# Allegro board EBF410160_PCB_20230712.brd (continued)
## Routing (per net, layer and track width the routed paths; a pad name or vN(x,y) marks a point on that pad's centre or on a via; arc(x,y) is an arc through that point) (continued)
VCC_RTC: length 54.7
  TOP w0.254: v1(25.53,39.62) 27.56,39.62 28.13,39.05 J4.18
  TOP w0.381: R51.2 19.81,70.22 19.81,67.82 19.05,67.05 19.05,65.41 v1(18.28,64.64)
  ART03 w0.381: v1(18.28,64.64) 15.75,62.11 15.75,53.34 19.52,49.57 19.52,45.64 25.53,39.63 v1(25.53,39.62)
VCCA_1V8: length 87.9
  TOP w0.254: v1(26.42,23.11) 26.63,23.33 J4.12 ; v1(9.53,38.35) 8.89,38.99 8.89,45.85 6.73,48 R227.2
  ART03 w0.508: v1(26.42,23.11) 26.42,24.13 23.7,26.85 17.86,26.85 14.86,29.84 13.72,29.84 11.18,32.38 10.03,32.38 9.65,32.76 9.65,38.23 v1(9.53,38.35)
  ART03 w0.635: v1(54.86,16.13) 53.59,14.86 36.8,14.86 31.72,19.94 26.54,19.94 25.74,20.74 25.74,22.44 v1(26.42,23.11)
  BOTTOM w0.254: R34.1 52.07,23.63 52.07,21.72 52.32,21.46 54.36,21.46 54.86,20.95 v1(54.86,16.13)
  BOTTOM w0.381: v1(26.42,23.11) C50.1
VCCIO_ACODEC: length 126
  TOP w0.254: J4.21 29.13,21.87 v1(28.89,22.11) 28.88,22.11 28.63,21.86 J4.19
  TOP w0.381: v1(43.18,82.29) 43.18,76.2 45.59,73.79 45.59,70.86 45.09,70.37 C177.1 R214.1 C172.1 R212.1
  ART03 w0.635: v1(28.89,22.11) 28.19,22.81 28.19,26.92 27.14,27.98 18.12,27.98 14.73,31.37 13.84,31.37 12.45,32.76 12.45,38.23 9.78,40.89 9.78,47.49 6.1,51.17 6.1,66.8 7.24,67.94 7.24,70.1 7.87,70.74 11.18,70.74 21.37,80.94 34.71,80.94 36.07,82.29 v1(43.18,82.29)
VDD_3V3: length 128.4
  TOP w0.254: v1(127.82,45.03) 127.81,45.01 126.32,45.01 R165.1 R169.1 ; LED4.2 LED3.2 LED2.2 v1(129.02,14.72)
  TOP w0.381: v1(86.31,37.22) C107.1 R127.1 88.85,37.22 Q7.2 ; v1(17.28,64.64) 16.38,65.54 16.38,67.47 D9.2 ; v1(94.79,54.85) C88.1 93.14,54.85 L5.2
  TOP w0.508: v1(12.19,23.11) 11.53,23.77 11.53,26.52 v1(12.19,27.18) 13.84,28.83 v1(14.99,28.83)
  ART03 w0.508: v1(23.88,37.21) 25.02,36.07 v1(36.96,36.07) v1(40.39,36.07)
  POW04 w0.686: J34.1 100.73,10.65 ; J34.1 99.27,10.65 ; J34.1 100,9.93 ; 75.27,10.65 J32.1 ; J32.1 76.73,10.65 ; J32.1 76,9.93 ; 87.27,10.65 J33.1 ; J33.1 88.73,10.65 ; J33.1 88,9.93 ; 112,9.93 J35.1 ; J35.1 111.27,10.65 ; J35.1 112.73,10.65
  BOTTOM w0.254: C59.1 11.79,26.81 U10.5 ; C59.1 R42.1 ; C59.1 v1(12.19,27.18) ; R167.1 R163.1 v1(125.74,72.13) ; U13.16 25.28,38.22 24.88,38.62 C67.1 ; C73.1 50.05,38.62 50.3,38.36 U14.8 ; U9.5 11.79,22.74 C57.1 ; R155.1 50.17,65.9 50.67,65.4 52.71,65.4 53.21,65.9 R156.1 ; C57.1 v1(12.19,23.11) ; C57.1 R38.1
  BOTTOM w0.381: R47.2 121.71,12.69 120.78,11.76 v1(120.78,10.29) ; v1(36.96,36.07) 37.46,36.57 R52.1 R53.1 R55.1 R54.1 ; v1(66.93,65.91) 66.94,65.9 R158.1 ; C73.1 48.58,38.62 D23.2 ; v1(54.23,65.9) R156.1 ; v1(128.06,12.82) 127.93,12.69 R44.1 ; v1(74.55,66.16) 74.8,65.9 C92.1 76.07,65.91 76.45,66.29 77.25,66.29 L6.2
  BOTTOM w0.508: v1(14.99,28.83) 20.32,28.83 21.33,29.84 C6.1 ; v1(95.63,54.86) 95.62,54.85 v1(94.79,54.85) 93.98,54.05 93.98,51.56 86.31,43.9 v1(86.31,37.22) ; v1(23.88,37.21) C67.1 ; J35.1 110.38,10.65 109.77,11.26 C75.1
  vias: v1(22.86,37.21) v1(106.81,56.13)
VDD_5V: length 91.8
  TOP w0.508: v1(50.67,76.83) 52.07,75.44 52.07,68.96 51.44,68.32 51.44,64.13 ; 51.44,64.13 v1(51.42,64.13) ; 51.44,64.13 51.94,63.63 56.52,63.63 57.53,64.64 v1(66.42,64.64)
  ART03 w0.889: v1(16.26,64.64) 16.26,65.92 21.08,70.74 21.08,76.07 24.38,79.37 34.54,79.37 37.08,76.83 v1(50.67,76.83)
  BOTTOM w0.254: v1(51.42,64.13) 51.98,64.13 Q8.1
  BOTTOM w0.508: D32.2 v1(66.42,64.64) ; v1(16.26,64.64) 16.26,62.62 15.11,61.47 15.11,57.53 16.38,56.26 19.43,56.26 20.07,55.62 20.07,53.78
B_DM1: length 13.9
  TOP w0.158: J18.11 93.74,77.17 92.85,76.28 92.85,74.94 91.97,74.06 91.26,74.06 90.68,73.48 90.68,72.9 v1(90.93,72.64)
  BOTTOM w0.158: R129.1 89.23,69.03 89.23,69.46 89.6,69.83 89.77,69.83 arc(89.87,69.87) 89.91,69.97 arc(89.95,70.06) 90.04,70.1 90.4,70.1 arc(90.5,70.06) 90.54,69.97 arc(90.58,69.87) 90.67,69.83 91.1,69.83 91.37,70.1 91.37,70.55 U18.5 U18.6 91.35,71.41 91.35,72.48 91.18,72.64 v1(90.93,72.64)
B_DM2: length 14.4
  BOTTOM w0.158: R138.1 107.19,70.58 U20.4 U20.7 107.08,71.51 107.08,72.91 108.23,74.07 109.74,74.07 110.57,74.9 110.57,76.41 110.89,76.73 112.03,76.73 112.71,77.4 112.71,77.77 112.86,77.92 113.09,77.92 J20.8
B_DM3: length 10.6
  BOTTOM w0.158: J20.2 113.34,75.49 112.6,74.75 112.6,74.14 111.23,72.77 109.22,72.77 108.63,72.17 108.63,71.98 108.7,71.92 U20.10 U20.1 108.7,69.09 R131.1
B_DP1: length 13.9
  TOP w0.158: v1(90.17,72.64) 90.32,72.79 90.32,73.63 91.11,74.42 91.82,74.42 92.49,75.09 92.49,77.03 J18.12
  BOTTOM w0.158: R130.1 89.59,68.77 89.59,69.31 89.75,69.47 91.25,69.47 91.73,69.95 91.73,70.49 U18.4 U18.7 91.71,71.51 91.71,72.63 91.19,73.14 90.67,73.14 v1(90.17,72.64)
B_DP2: length 14.3
  BOTTOM w0.158: R139.1 106.17,69.34 106.7,69.86 U20.5 U20.6 106.7,71.64 106.72,71.66 106.72,73.06 108.08,74.43 109.59,74.43 110.21,75.05 110.21,76.56 110.74,77.09 111.88,77.09 112.34,77.55 112.34,77.8 J20.9
B_DP3: length 10.1
  BOTTOM w0.158: R132.1 108.33,68.7 108.33,70.1 108.2,70.24 U20.2 U20.9 108.2,71.92 108.27,71.98 108.27,72.32 109.07,73.13 111.08,73.13 112.24,74.29 112.24,74.9 J20.3
BD_CH3: length 4.5
  TOP w0.156: J6.20 v1(53.63,26.1)
  BOTTOM w0.254: v1(53.63,26.1) 53.59,26.07 C53.1 ; R35.1 C53.1 ; C53.1 R34.2
CAM0_NRST: length 105.9
  TOP w0.156: J7.35 57.63,62.84 57.91,63.12 69.98,63.12 70.23,62.86 v1(70.23,61.47)
  ART03 w0.142: v1(135,78.59) 135.68,77.91 135.68,66.21 132.72,63.24 128.65,63.24 127.08,61.68 125.55,61.68 125.13,62.1 112.39,62.1 112.01,62.48 101.09,62.48 98.55,59.94 85.6,59.94 84.12,58.46 77.39,58.46 76.07,57.15 72.14,57.15 70.23,59.05 v1(70.23,61.47)
  BOTTOM w0.156: J23.22 131.12,78.16 131.55,78.59 v1(135,78.59)
CAM0_PWDN: length 126.3
  TOP w0.156: v1(38.63,54.1) 37.63,55.1 J5.56
  ART03 w0.142: v1(133.35,57.4) 119,57.4 118.36,56.77 117.6,56.77 116.46,55.62 112.14,55.62 107.31,50.8 102.11,50.8 101.93,50.62 94.05,50.62 93.6,50.16 78.36,50.16 77.34,51.18 60.07,51.18 58.04,53.21 49.91,53.21 49.53,53.59 39.14,53.59 v1(38.63,54.1)
  BOTTOM w0.156: v1(133.35,57.4) 135.64,59.69 135.64,74.04 135.02,74.66 J23.15
CAM0_PWR_EN: length 78.7
  TOP w0.156: v1(81.53,39.88) 68.13,26.47 J6.78 ; v1(122.05,56.89) 122.05,56.39 121.28,55.62 v1(121.28,46.86)
  ART03 w0.142: v1(121.28,46.86) 120.78,46.35 118.24,46.35 117.73,45.85 116.2,45.85 114.14,43.78 114.14,42.45 113.8,42.12 112.31,42.12 110.45,40.26 81.92,40.26 v1(81.53,39.88)
  BOTTOM w0.156: v1(122.05,56.89) 121.54,57.4 R179.1
CAM1_NRST: length 78.6
  TOP w0.156: J7.41 59.13,59.59 v1(58.63,59.09)
  ART03 w0.142: v1(129.29,61.39) 127.96,60.07 105.66,60.07 102.74,57.15 90.96,57.15 90.16,56.34 85.68,56.34 84.69,55.35 67.84,55.35 65.53,57.66 64.26,57.66 63.37,58.55 59.18,58.55 v1(58.63,59.09)
  BOTTOM w0.156: J24.22 v1(129.29,61.39)
CAM1_PWDN: length 78.7
  TOP w0.156: v1(65.13,59.09) 64.63,59.59 J7.63
  ART03 w0.142: v1(131.95,60.32) 130.3,61.97 128.91,61.97 128.02,61.09 112.78,61.09 111.76,62.1 101.47,62.1 98.76,59.39 85.93,59.39 83.95,57.4 81.79,57.4 81.28,57.91 77.47,57.91 76.3,56.75 69.11,56.75 66.33,59.52 65.56,59.52 v1(65.13,59.09)
  BOTTOM w0.156: v1(131.95,60.32) 131.95,58.29 131.55,57.89 J24.15
CAM1_PWR_EN: length 116.5
  TOP w0.156: J5.12 26.63,55.21 v1(25.63,54.21)
  ART03 w0.142: v1(25.63,54.21) 25.63,47.01 26.8,45.85 50.67,45.85 55.76,40.76 69.85,40.76 70.36,41.27 92.58,41.27 93.22,41.91 v1(108.97,41.91)
  BOTTOM w0.156: R186.1 118.27,51.56 118.11,51.4 118.11,49.4 117.22,48.51 109.6,48.51 108.97,47.88 v1(108.97,41.91)
CC1: length 6.1
  TOP w0.156: v1(28.83,84.83) 28.58,84.58 J19.A5
  BOTTOM w0.156: v1(28.83,84.83) 28.83,82.68 29.62,81.89 D29.2
CC2: length 14.9
  TOP w0.156: J19.B5 v1(25.58,84.78)
  BOTTOM w0.156: v1(25.58,84.78) 25.58,86.03 25.91,86.36 28.96,86.36 29.34,85.98 29.34,82.93 30.54,81.72 30.54,79.98 D29.1
CSI_RX_D2N_S0: length 4.9
  BOTTOM w0.124: R178.2 126.28,76.15 126.8,76.15 127.38,75.57 129.51,75.57 129.6,75.66 J23.17
CSI_RX_D2N_S1: length 38.1
  TOP w0.124: v1(123.7,72.77) 123.7,73.05 122.64,74.1 122.64,74.11 122.23,74.52 122.23,75.8 122.54,76.11 122.88,76.11 v1(123.05,76.28)
  BOTTOM w0.124: R180.2 123.65,76.12 123.2,76.12 v1(123.05,76.28) ; v1(123.7,72.77) 123.7,73.03 123.38,73.34 123.21,73.34 121.98,72.12 arc(121.95,72.04) 121.98,71.97 arc(122.01,71.89) 121.98,71.82 121.78,71.62 arc(121.71,71.59) 121.63,71.62 arc(121.56,71.65) 121.48,71.62 121.28,71.42 arc(121.25,71.34) 121.28,71.27 arc(121.31,71.19) 121.28,71.12 121.08,70.91 arc(121.01,70.88) 120.93,70.91 arc(120.86,70.95) 120.78,70.91 120.27,70.4 120.27,69.79 120.39,69.67 121.73,69.67 122.05,69.35 122.05,68.83 121.73,68.52 120.39,68.52 120.14,68.27 120.14,57.53 121.37,56.3 129.51,56.3 129.6,56.39 J24.12
CSI_RX_D2P_S0: length 4.9
  BOTTOM w0.124: R176.2 126.36,75.82 126.66,75.82 127.24,75.24 129.51,75.24 129.6,75.16 J23.16
CSI_RX_D2P_S1: length 38.2
  TOP w0.124: v1(124.21,73.28) 123.93,73.28 122.97,74.24 122.97,74.24 122.56,74.66 122.56,75.66 122.68,75.78 122.88,75.78 v1(123.05,75.62)
  BOTTOM w0.124: R177.2 123.63,75.78 123.27,75.78 123.11,75.62 v1(123.05,75.62) ; v1(124.21,73.28) 123.91,73.28 123.52,73.67 123.07,73.67 119.94,70.54 119.94,69.66 120.26,69.34 121.6,69.34 121.72,69.22 121.72,68.97 121.6,68.85 120.26,68.85 119.81,68.4 119.81,57.39 121.23,55.98 129.51,55.98 129.6,55.89 J24.11
CSI_RX_D3N_S0: length 5.1
  BOTTOM w0.124: J23.20 129.6,77.16 129.51,77.07 128.42,77.07 127.34,78.14 126.32,78.14 R184.2
CSI_RX_D3N_S1: length 38.1
  TOP w0.124: v1(121.03,72.77) 121.03,73.79 121.28,74.04 121.28,77.29 122.14,78.14 122.88,78.14 v1(123.05,78.31)
  BOTTOM w0.124: R185.2 123.63,78.14 123.22,78.14 v1(123.05,78.31) ; v1(121.03,72.77) 121.03,72.95 121.02,72.95 120.9,73.08 120.45,73.08 119.25,71.88 119.25,71.63 arc(119.31,71.5) 119.44,71.44 arc(119.53,71.4) 119.57,71.32 119.57,71.07 arc(119.53,70.98) 119.44,70.94 arc(119.31,70.89) 119.25,70.75 119.25,56.89 121.84,54.3 129.51,54.3 129.6,54.39 J24.8
CSI_RX_D3P_S0: length 5.1
  BOTTOM w0.124: R182.2 126.32,77.81 127.21,77.81 128.28,76.74 129.51,76.74 129.6,76.66 J23.19
CSI_RX_D3P_S1: length 38
  TOP w0.124: v1(121.54,73.28) 121.61,73.35 121.61,77.15 122.28,77.82 122.88,77.82 v1(123.05,77.65)
  BOTTOM w0.124: J24.7 129.6,53.89 129.51,53.98 121.71,53.98 118.93,56.76 118.93,72.02 120.31,73.4 121.03,73.4 121.16,73.28 v1(121.54,73.28) ; R183.2 123.63,77.81 123.28,77.81 123.11,77.65 v1(123.05,77.65)
CTP0_INT: length 134.9
  TOP w0.156: J21.11 128.81,69.12 v1(128.02,68.32) 122.43,68.32 118.75,64.64 118.75,52.2 119.25,51.69 119.25,49.4 118.24,48.39 v1(118.24,44.83) ; J6.65 v1(65.13,19.18)
  ART03 w0.142: v1(118.24,44.83) 118.36,44.7 118.36,43.05 123.7,37.72 127,37.72 129.03,35.68 129.03,19.94 126.11,17.02 121.54,17.02 119.89,15.37 78.49,15.37 77.98,15.87 74.3,15.87 70.99,19.18 v1(65.13,19.18)
  BOTTOM w0.156: v1(128.02,68.32) R162.2
CTP0_RST: length 139.9
  TOP w0.156: J21.12 v1(128.07,69.62) 128.07,69.62 127.28,68.83 122.3,68.83 118.21,64.74 118.21,49.17 117.73,48.69 117.73,45.34 v1(117.22,44.83) ; J6.61 v1(64.13,19.18)
  ART03 w0.142: v1(117.22,44.83) 117.73,45.34 118.49,45.34 118.75,45.08 118.75,43.31 122.94,39.11 126.36,39.11 129.54,35.94 129.54,19.81 126.24,16.51 121.67,16.51 120.02,14.86 78.11,14.86 77.69,15.28 74.13,15.28 70.74,18.67 64.64,18.67 v1(64.13,19.18)
  BOTTOM w0.156: v1(128.07,69.62) 127.79,69.34 R166.2
CTP1_INT: length 111.7
  TOP w0.156: J7.55 v1(62.63,60.11) ; R164.2 127.31,47.62 v1(127.91,47.03) J22.11
  BOTTOM w0.156: v1(127.91,47.03) 128.37,47.49 128.37,48.23 128.09,48.51 118.49,48.51 117.86,47.88 112.39,47.88 109.86,45.34 109.86,34.59 109.43,34.16 94.92,34.16 93.4,32.64 77.85,32.64 64.66,45.83 61.61,45.83 57.66,49.78 57.66,55.82 58.43,56.6 61.42,56.6 63.11,58.29 63.11,59.63 v1(62.63,60.11)
CTP1_RST: length 110.9
  TOP w0.156: J7.57 63.13,59.59 v1(62.63,59.09) ; J22.12 128.39,47.53 v1(127.89,48.02) 127.27,48.64 R168.2
  BOTTOM w0.156: v1(62.63,59.09) 62.63,58.44 61.21,57.02 58.04,57.02 57.15,56.13 57.15,49.53 61.3,45.38 64.35,45.38 77.6,32.13 93.65,32.13 95.17,33.65 109.64,33.65 110.36,34.38 110.36,45.08 112.65,47.37 118.11,47.37 118.77,48.02 v1(127.89,48.02)
DBG_RX: length 2.8
  BOTTOM w0.156: R40.2 8.88,25.91 9.86,25.91 10.29,25.48 U10.2
DBG_RXD: length 5.5
  BOTTOM w0.156: J9.3 3.52,25.41 D6.2 R40.1
DBG_TX: length 1.4
  BOTTOM w0.156: R39.2 8.78,22.74 U9.4
DBG_TXD: length 5.8
  BOTTOM w0.156: R39.1 D5.2 6.32,22.39 J9.2
DM4: length 9.5
  TOP w0.158: J27.36 98.8,61.91 98.58,61.69 98.58,59.59 98.74,59.43 99.06,59.43 99.31,59.18 D38.2 98.84,58.66 98.68,58.51 98.68,57.15 98.15,56.62 98.15,55.76 98.28,55.63 98.57,55.63 R210.1
DP4: length 10.4
  TOP w0.158: R211.1 98.43,55.24 98.16,55.24 97.79,55.61 97.79,56.77 98.32,57.3 98.32,58.51 98.16,58.66 D39.2 97.66,59.28 97.82,59.43 98.04,59.43 98.22,59.61 98.22,60.32 arc(98.18,60.42) 98.07,60.47 arc(97.96,60.51) 97.92,60.62 97.92,60.95 arc(97.96,61.06) 98.07,61.1 arc(98.18,61.15) 98.22,61.25 98.22,61.69 98,61.91 J27.38
DSI0_RST: length 107.5
  TOP w0.156: J5.60 v1(38.63,56.13) ; J21.15 122.43,71.12 116.71,65.4 116.71,61.72 115.82,60.83 115.82,57.02 v1(115.44,56.64)
  ART03 w0.142: v1(115.44,56.64) 111.51,56.64 107.03,52.16 93.51,52.16 92.61,51.26 78.53,51.26 77.77,52.02 63.29,52.02 61.72,53.59 59.18,53.59 58.12,54.65 40.11,54.65 v1(38.63,56.13)
DSI0_TE: length 102
  TOP w0.156: J5.58 38.13,55.62 v1(38.63,55.12) ; R160.1 122.3,70.23 117.22,65.15 117.22,61.21 116.59,60.58 v1(116.59,56.64)
  ART03 w0.142: v1(116.59,56.64) 116.08,56.13 111.89,56.13 107.5,51.75 102.17,51.75 101.6,51.18 97.92,51.18 97.62,51.48 93.77,51.48 93.11,50.82 78.34,50.82 77.58,51.58 62.85,51.58 61.34,53.08 58.93,53.08 58.29,53.72 50.16,53.72 49.78,54.1 39.65,54.1 v1(38.63,55.12)
DSI1_RST: length 115.4
  TOP w0.156: J22.15 128.47,49.02 127.2,50.29 122.43,50.29 121.77,49.63 121.77,46.33 v1(121.28,45.85) ; v1(61.63,59.09) 62.13,59.59 J7.53
  BOTTOM w0.156: v1(61.63,59.09) 61.63,58.71 60.71,57.78 57.28,57.78 56.13,56.64 56.13,49.1 60.91,44.32 63.5,44.32 76.71,31.11 94.28,31.11 95.68,32.51 110.11,32.51 111.38,33.78 111.38,44.58 112.65,45.85 118.11,45.85 118.59,46.33 120.8,46.33 v1(121.28,45.85)
DSI1_TE: length 108.6
  TOP w0.156: R161.1 122.81,49.66 122.3,49.15 v1(122.3,46.86) ; J7.51 v1(61.63,60.11)
  BOTTOM w0.156: v1(122.3,46.86) 121.82,47.35 118.85,47.35 117.86,46.35 112.39,46.35 110.87,44.83 110.87,34.17 109.85,33.15 95.55,33.15 94.03,31.62 77.22,31.62 64.01,44.83 61.09,44.83 56.64,49.27 56.64,56.39 57.66,57.4 60.96,57.4 62.11,58.56 62.11,59.63 v1(61.63,60.11)
EDP_AUXN: length 7.6
  TOP w0.124: C146.2 123.69,24.42 123.81,24.29 126.74,24.29 126.86,24.42 R191.2 127.25,24.89 127.8,24.34 129.06,24.34 129.14,24.43 J25.10
EDP_AUXP: length 7.6
  TOP w0.124: C147.2 123.69,23.84 123.81,23.97 126.74,23.97 126.86,23.84 R188.2 127.25,23.37 127.9,24.01 129.06,24.01 129.14,23.93 J25.9
EDP_BL_EN: length 118.3
  TOP w0.156: J25.22 130.89,30.43 v1(131.06,30.61) ; v1(33.63,19.05) J4.39
  ART03 w0.142: v1(33.63,19.05) 34.65,18.03 50.29,18.03 51.18,17.14 68.45,17.14 72.77,12.83 120.65,12.83 122.43,14.6 127.38,14.6 132.21,19.43 132.21,28.7 131.7,29.21 131.7,29.97 v1(131.06,30.61)
EDP_BL_PWM: length 134.9
  TOP w0.156: J5.5 25.13,63.26 v1(26.13,64.26) ; v1(127.89,31.24) 128.2,30.93 J25.23
  ART03 w0.142: v1(26.13,64.26) 25.65,63.78 25.65,55.12 25.15,54.61 25.15,46.74 27.3,44.58 51.18,44.58 56.39,39.37 110.87,39.37 111.25,39.75 112.52,39.75 114.35,37.92 120.83,37.92 122.94,35.81 127.13,35.81 127.89,35.05 v1(127.89,31.24)
EDP_HPDIN_M0: length 99.2
  TOP w0.156: v1(68.45,31.49) 65.13,28.17 J6.66 ; J25.17 v1(131.7,27.93)
  ART03 w0.142: v1(73.41,13.69) 73.76,13.33 120.52,13.33 122.3,15.11 127.13,15.11
  ART03 w0.156: 127.13,15.11 131.7,19.68 v1(131.7,27.93)
  BOTTOM w0.156: v1(68.45,31.49) 71.12,28.83 71.12,28.45 71.2,28.37 71.2,27.97 71.12,27.89 71.12,20.45 73.41,18.16 v1(73.41,13.69)
EDP_PWR_EN: length 69.4
  TOP w0.156: R196.1 118.57,27.68 118.31,27.93 118.31,36.57 117.68,37.21 112.52,37.21 v1(112.01,37.72) ; v1(78.36,37.72) 67.63,26.99 J6.76
  ART03 w0.142: v1(78.36,37.72) v1(112.01,37.72)
  BOTTOM w0.156: v1(112.01,37.72) R192.1
EDP_TP_INT: length 114
  TOP w0.156: J7.65 v1(65.13,60.11) ; v1(88.9,33.27) 88.9,12.95 88.39,12.44 69.85,12.44 68.96,11.56 68.96,10.2 68.41,9.65 63,9.65 J26.2
  BOTTOM w0.156: v1(88.9,33.27) 77.98,33.27 65.02,46.23 61.98,46.23 58.29,49.91 58.29,54.95 59.48,56.13 61.47,56.13 61.97,56.64 62.23,56.64 64.26,58.67 64.26,59.24 v1(65.13,60.11) ; J26.2 63.37,12.03 63.37,18.03 61.84,19.57 R189.2
EDP_TP_RESET: length 15.2
  TOP w0.156: J6.57 v1(63.13,22.1)
  BOTTOM w0.156: R190.2 62.37,21.33 v1(63.13,22.1) 63.63,21.6 63.63,18.67 64.39,17.91 64.39,11.04 J26.3
EDP_TX_AUXN: length 81.1
  TOP w0.124: J6.62 64.13,25.81 64.06,25.88 64.06,29.26 64.91,30.11 64.91,31.18 v1(65.1,31.37) ; v1(120,22.2) 120.14,22.34 120.14,23.75 120.69,24.29 122.57,24.29 122.69,24.42 C146.1
  ART03 w0.113: v1(65.1,31.37) 64.77,31.7 64.77,32.06 65.15,32.45 65.61,32.45 arc(65.68,32.42) 65.71,32.35 arc(65.74,32.29) 65.8,32.26 66.06,32.26 arc(66.13,32.29) 66.16,32.35 arc(66.19,32.42) 66.25,32.45 66.51,32.45 arc(66.58,32.42) 66.61,32.35 arc(66.64,32.29) 66.71,32.26 66.96,32.26 arc(67.03,32.29) 67.06,32.35 arc(67.09,32.42) 67.16,32.45 96.14,32.45 97.92,34.23 116.2,34.23 117.72,32.71 117.72,27.51 118.78,26.44 118.78,26.29 118.34,25.85 118.34,25.43 118.68,25.08 119.1,25.08 119.54,25.52 119.7,25.52 120.21,25.01 120.21,22.4 120.01,22.2 v1(120,22.2)
EDP_TX_AUXP: length 81
  TOP w0.124: J6.60 63.63,25.78 63.73,25.88 63.73,29.4 64.58,30.24 64.58,31.23 v1(64.44,31.37) ; v1(120.66,22.2) 120.47,22.4 120.47,23.61 120.82,23.97 122.57,23.97 122.69,23.84 C147.1
  ART03 w0.113: v1(64.44,31.37) 64.45,31.38 64.45,32.2 65.02,32.76 96.01,32.76 97.79,34.54 116.33,34.54 118.03,32.84 118.03,27.64 119.09,26.58 119.09,26.15 118.65,25.72 118.65,25.56 118.81,25.4 118.97,25.4 119.41,25.84 119.83,25.84 120.52,25.14 120.52,22.34 v1(120.66,22.2)
EDP_TX_D0N: length 88.8
  TOP w0.124: v1(128.51,22.35) 128.69,22.53 129.88,22.53 J25.6 ; J6.44 59.63,25.81 59.54,25.9 59.54,31.2 v1(59.71,31.37)
  ART03 w0.113: v1(128.51,22.35) 128.21,22.65 127.4,22.65 126.08,23.97 124.04,23.97 119.45,28.57 119.45,33.46 116.33,36.57 97.35,36.57 95.89,35.12 62.55,35.12 59.54,32.1 59.54,31.54 v1(59.71,31.37)
EDP_TX_D0P: length 89.2
  TOP w0.124: v1(128.51,23.01) 128.66,22.86 129.92,22.86 J25.7 ; v1(59.05,31.37) 59.22,31.2 59.22,25.9 59.13,25.81 J6.42
  ART03 w0.113: v1(59.05,31.37) 59.22,31.54 59.22,32.24 62.42,35.43 95.76,35.43 97.22,36.89 116.46,36.89 119.76,33.59 119.76,28.7 124.18,24.29 126.21,24.29 127.53,22.96 128.46,22.96 v1(128.51,23.01)
EDP_TX_D1N: length 90.1
  TOP w0.124: v1(62.36,31.37) 62.17,31.18 62.17,29.91 60.54,28.28 60.54,25.9 60.63,25.81 J6.48 ; J25.3 129.88,21.03 126.79,21.03 v1(126.6,20.85)
  ART03 w0.113: v1(126.6,20.85) 126.36,21.1 125.52,21.1 124.21,22.4 124.05,22.4 123.57,21.92 123.15,21.92 122.8,22.26 122.8,22.68 123.29,23.17 123.29,23.33 123.13,23.49 122.97,23.49 122.55,23.07 122.13,23.07 121.78,23.41 121.78,23.83 122.2,24.26 122.2,24.41 118.54,28.08 118.54,33.1 116.52,35.12 97.41,35.12 96.27,33.97 63.31,33.97 62.1,32.76 62.1,31.63 v1(62.36,31.37)
EDP_TX_D1P: length 90.5
  TOP w0.124: J25.4 129.92,21.36 126.75,21.36 v1(126.6,21.51) ; v1(61.7,31.37) 61.84,31.23 61.84,30.05 60.22,28.42 60.22,25.9 60.13,25.81 J6.46
  ART03 w0.113: v1(61.7,31.37) 61.79,31.45 61.79,32.9 63.18,34.29 96.14,34.29 97.28,35.43 116.65,35.43 118.86,33.23 118.86,28.21 122.52,24.55 122.52,24.12 122.1,23.7 122.1,23.54 122.26,23.38 122.42,23.38 122.84,23.81 123.26,23.81 123.6,23.46 123.6,23.04 123.12,22.55 123.12,22.39 123.28,22.23 123.44,22.23 123.92,22.72 124.34,22.72 125.65,21.41 126.51,21.41 v1(126.6,21.51)
EXT_PWR_EN: length 81.8
  TOP w0.156: J4.27 v1(30.63,22.1) ; v1(14.48,37.84) 13.72,38.61 R19.1
  ART03 w0.142: v1(30.63,22.1) 30.63,27.51 28.02,30.12 20.09,30.12 15.72,34.49 14.53,34.49 13.97,35.05 13.97,37.34 v1(14.48,37.84) 14.99,38.35 14.99,42.92 15.62,43.56 v1(15.62,45.72) 15.62,48.39 10.03,53.97 10.03,67.05 v1(9.4,67.69)
  BOTTOM w0.156: R3.1 15.75,48.51 15.62,48.39 v1(15.62,45.72) 20.95,45.72 21.33,45.35 R1.1 ; R24.1 5.2,67.45 9.16,67.45 v1(9.4,67.69)
FSPI_CLK: length 36
  TOP w0.156: U8.6 82.42,25.4 v1(80.14,27.68) ; v1(56.63,23.12) 56.13,22.62 J6.29
  ART03 w0.142: v1(56.63,23.12) 56.63,24.24 57.91,25.53 59.48,25.53 59.62,25.67 59.62,26.02 59.77,26.16 60.05,26.16 60.19,26.02 60.19,25.67 60.34,25.53 60.62,25.53 60.76,25.67 60.76,26.02 60.91,26.16 61.19,26.16 61.33,26.02 61.33,25.67 61.48,25.53 68.65,25.53 70.81,27.68 v1(80.14,27.68)
FSPI_CS0N: length 36.2
  TOP w0.156: J6.31 v1(56.63,22.1) ; v1(83.69,27.68) 84.96,28.95 U8.1
  ART03 w0.142: v1(56.63,22.1) 57.13,22.6 57.13,23.85 58.29,25.02 68.96,25.02 71.12,27.18 81.03,27.18 82.04,28.19 83.19,28.19 v1(83.69,27.68)
FSPI_D0: length 45.1
  TOP w0.156: J6.33 57.13,22.62 v1(57.63,23.12) ; v1(80.14,26.67) 81.15,25.65 U8.5
  ART03 w0.142: v1(80.14,26.67) 80.14,25.91 80.01,25.78 79.63,25.78 79.5,25.91 79.5,26.54 79.38,26.67 79.03,26.67 78.89,26.53 78.89,25.92 78.74,25.78 78.46,25.78 78.32,25.92 78.32,26.53 78.17,26.67 77.89,26.67 77.75,26.53 77.75,25.92 77.6,25.78 77.32,25.78 77.18,25.92 77.18,26.53 77.03,26.67 71.44,26.67 69.16,24.38 58.29,24.38 57.63,23.72 v1(57.63,23.12)
  BOTTOM w0.156: J8.2 81.79,25.02 v1(80.14,26.67)
FSPI_D1: length 36.1
  TOP w0.156: J6.35 v1(57.63,22.1) ; 83.69,31.3 83.69,28.95 v1(82.42,27.68)
  ART03 w0.142: v1(82.42,27.68) 81.41,26.67 80.91,26.67 80.77,26.53 80.77,26.16 80.9,26.03 81.41,26.03 81.53,25.91 81.53,25.41 81.39,25.27 77.09,25.27 76.2,26.16 71.64,26.16 69.36,23.87 58.42,23.87 58.15,23.61 58.15,22.63 v1(57.63,22.1)
FSPI_D2: length 46.2
  TOP w0.156: v1(58.63,23.12) 58.13,22.62 J6.37 ; R36.2 87.5,32.38 87,32.89 82.8,32.89 82.42,32.51 U8.3 82.42,29.59 81.79,28.95 81.79,27.3 v1(82.42,26.67)
  ART03 w0.142: v1(82.42,26.67) 83.04,26.67 83.19,26.53 83.19,26.16 83.06,26.03 82.18,26.03 82.04,25.89 82.04,25.02 81.79,24.76 76.83,24.76 75.95,25.65 71.84,25.65 69.56,23.37 58.88,23.37 v1(58.63,23.12)
FSPI_D3: length 39.6
  TOP w0.156: J6.39 v1(58.63,22.1) ; R37.2 85.97,28.95 v1(83.69,26.67) 83.69,23.3
  ART03 w0.142: v1(58.63,22.1) 59.38,22.86 69.72,22.86 72.01,25.14 75.69,25.14 76.58,24.26 83.55,24.26 83.69,24.4 83.69,24.76 83.57,24.89 82.68,24.89 82.55,25.02 82.55,25.38 82.69,25.53 83.57,25.53 83.69,25.65 v1(83.69,26.67)
GMAC1_INT: length 106.7
  TOP w0.156: v1(24.13,54.21) 24.74,54.21 26.13,55.59 J5.10 ; R111.1 90.55,55.88 90.81,55.62 91.95,55.62 92.33,56.01 93.6,56.01 93.98,55.62 96.01,55.62 96.27,55.37 96.27,53.47 v1(95.63,52.83)
  ART03 w0.142: v1(95.63,52.83) 91.82,52.83 91.44,52.45 64.64,52.45 63.58,53.51 62.95,53.51 60.82,55.64 40.88,55.64 40.64,55.88 40.64,56.26 40.26,56.64 39.75,56.64 34.16,62.23 34.16,66.29 33.15,67.31 26.67,67.31 25.15,65.78 25.15,55.22 v1(24.13,54.21)
GMAC1_MCLKINOUT_M1: length 48.6
  TOP w0.156: R112.1 R113.1 v1(95.12,56.13) ; J7.56 62.63,55.35 63.37,54.61 64.11,54.61 64.39,54.33 v1(64.39,48.41)
  BOTTOM w0.156: v1(95.12,56.13) 94.64,55.65 93.8,55.65 92.08,53.92 92.08,51.56 87.5,46.99 79.88,46.99 78.46,48.41 v1(64.39,48.41)
GMAC1_MDC_M1: length 24
  TOP w0.156: v1(64.63,55.09) 64.13,55.59 J7.62 ; U16.13 79.87,58.16 79.12,58.16 77.98,57.02 v1(77.98,56.95) 77.85,56.82 77.85,54.73 R108.2
  BOTTOM w0.156: v1(77.98,56.95) 76.66,55.62 66.06,55.62 65.53,55.09 v1(64.63,55.09)
GMAC1_MDIO_M1: length 25
  TOP w0.156: U16.14 79.21,56.95 v1(78.99,56.95) 78.36,56.31 78.36,54.86 78.87,54.35 79.24,54.35 R109.2 ; J7.60 v1(63.63,56.11)
  BOTTOM w0.156: v1(78.99,56.95) 78.41,57.53 77.72,57.53 76.33,56.13 65.79,56.13 65.28,55.62 64.12,55.62 v1(63.63,56.11)
GMAC1_RSTN: length 67.6
  TOP w0.156: J5.4 24.63,58.28 24.64,58.29 v1(24.64,59.18)
  BOTTOM w0.156: v1(24.64,59.18) 24.64,47.62 25.91,46.35 47.5,46.35 48.64,47.5 48.64,58.8 51.68,61.84 C84.1 65.21,61.84 D28.1
GMAC1_RXCLK_M1: length 37.4
  TOP w0.156: R101.1 v1(86.11,51.81) R95.2 ; J7.36 57.63,54.51 59.18,52.96 60.96,52.96 61.98,51.94 v1(61.98,49.91)
  BOTTOM w0.156: v1(61.98,49.91) 62.46,49.43 76.35,49.43 76.71,49.78 84.07,49.78 v1(86.11,51.81)
GMAC1_RXD0_M1: length 38.8
  TOP w0.156: v1(59.56,52.45) 58.8,52.45 57.13,54.12 J7.34 ; R93.2 v1(84.07,51.81) R96.1
  BOTTOM w0.156: v1(59.56,52.45) 59,51.89 59,51.67 59.21,51.46 59.43,51.46 59.92,51.94 67.51,51.94 67.67,52.1 67.67,52.34 67.82,52.5 68.14,52.5 68.29,52.34 68.29,52.1 68.45,51.94 68.76,51.94 68.92,52.1 68.92,52.34 69.08,52.5 69.39,52.5 69.55,52.34 69.55,52.1 69.7,51.94 70.01,51.94 70.17,52.1 70.17,52.34 70.33,52.5 70.64,52.5 70.8,52.34 70.8,52.1 70.95,51.94 73.41,51.94 74.04,52.58 80.55,52.58 80.7,52.73 80.7,53.31 80.86,53.47 81.17,53.47 81.33,53.31 81.33,52.61 81.49,52.45 83.44,52.45 v1(84.07,51.81)
GMAC1_RXD1_M1: length 36.3
  TOP w0.156: R94.2 v1(83.06,51.81) R97.1 ; J7.32 56.63,53.86 58.55,51.94 61.09,51.94 61.34,51.69 61.34,50.67 v1(60.58,49.91)
  BOTTOM w0.156: v1(60.58,49.91) 61.16,50.5 76.09,50.5 76.32,50.72 81.96,50.72 v1(83.06,51.81)
GMAC1_RXD2_M1: length 37.2
  TOP w0.156: v1(59.56,49.91) 59.56,50.24 59.99,50.67 60.68,50.67 60.83,50.83 60.83,51.28 60.68,51.43 58.29,51.43 57.95,51.78 57.57,51.78 57.32,52.03 57.32,52.41 57.07,52.66 56.68,52.66 56.43,52.91 56.43,53.29 56.13,53.6 J7.30 ; R103.1 v1(82.04,51.81) R99.1
  BOTTOM w0.156: v1(59.56,49.91) 60.62,50.96 75.9,50.96 76.12,51.19 81.42,51.19 v1(82.04,51.81)
GMAC1_RXD3_M1: length 36.4
  TOP w0.156: v1(59.56,50.93) 57.66,50.93 57.29,51.3 57.03,51.3 56.72,51.61 56.72,51.87 56.4,52.18 56.15,52.18 55.83,52.5 55.83,52.75 55.63,52.95 J7.28 ; R100.1 v1(81.03,51.81) R104.1
  BOTTOM w0.156: v1(81.03,51.81) 80.73,52.11 80.44,52.11 80.28,51.95 80.28,51.82 80.12,51.66 79.81,51.66 79.65,51.82 79.65,51.95 79.5,52.11 79.18,52.11 79.03,51.95 79.03,51.82 78.87,51.66 78.56,51.66 78.4,51.82 78.4,51.95 78.24,52.11 77.93,52.11 77.78,51.95 77.78,51.82 77.62,51.66 77.31,51.66 77.15,51.82 77.15,51.95 76.99,52.11 76.68,52.11 76.52,51.95 76.52,51.82 76.37,51.66 76.05,51.66 75.9,51.82 75.9,51.95 75.74,52.11 75.46,52.11 75.3,51.95 75.3,51.59 75.14,51.43 74.83,51.43 74.68,51.59 74.68,51.95 74.52,52.11 74.24,52.11 73.6,51.47 60.11,51.47 v1(59.56,50.93)
GMAC1_RXDV_CRS_M1: length 38.9
  TOP w0.156: v1(63.12,49.91) 62.61,50.42 62.61,50.85 62.77,51 63.6,51 63.75,51.16 63.75,51.47 63.6,51.63 62.77,51.63 62.61,51.79 62.61,52.32 61.47,53.47 59.44,53.47 58.13,54.77 J7.38 ; R105.1 v1(85.09,51.81) R102.1
  BOTTOM w0.156: v1(63.12,49.91) 76.17,49.91 76.51,50.25 83.47,50.25 83.63,50.41 83.63,50.61 83.25,50.99 83.25,51.21 83.47,51.43 83.69,51.43 84.27,50.86 84.49,50.86 85.09,51.46 v1(85.09,51.81)
GMAC1_TXCLK_M1: length 29.5
  TOP w0.156: J7.44 v1(59.63,54.1) ; U16.20 81.92,56.25 81.92,55.8 v1(81.03,54.92)
  BOTTOM w0.156: v1(81.03,54.92) 81.03,54.48 79.61,53.06 67.41,53.06 66.93,52.58 61.21,52.58 60.83,52.96 60.2,52.96 59.63,53.53 v1(59.63,54.1)
GMAC1_TXD0_M1: length 25.5
  TOP w0.156: U16.18 80.94,56.42 80.79,56.42 80.52,56.15 80.52,55.42 v1(80.01,54.92) ; J7.52 61.63,55.24 61.88,54.99 62.23,54.99 62.48,54.74 62.48,54.38 62.79,54.08 v1(63.12,54.08)
  BOTTOM w0.156: v1(80.01,54.92) 79.53,55.4 78.77,55.4 77.98,54.61 66.55,54.61 66.02,54.08 v1(63.12,54.08)
GMAC1_TXD1_M1: length 27.3
  TOP w0.156: U16.17 80.73,56.77 80.52,56.77 80.01,56.26 v1(80.01,55.93) ; J7.50 61.13,55.07 v1(63.12,53.08)
  BOTTOM w0.156: v1(80.01,55.93) 80.52,55.42 80.52,54.74 79.36,53.58 67.04,53.58 66.55,53.08 v1(63.12,53.08)
GMAC1_TXD2_M1: length 28.2
  TOP w0.156: U16.16 80.55,57.15 80.39,57.15 79.5,56.26 79.5,55.42 v1(78.99,54.92) ; J7.48 v1(60.63,55.09)
  BOTTOM w0.156: v1(78.99,54.92) 78.18,54.1 66.8,54.1 66.29,53.59 62.13,53.59 61.98,53.44 61.98,53.24 61.82,53.08 61.51,53.08 61.35,53.24 61.35,53.44 61.19,53.59 60.33,53.59 60.15,53.77 60.15,54.61 v1(60.63,55.09)
GMAC1_TXD3_M1: length 28.6
  TOP w0.156: U16.15 80.36,57.53 80.26,57.53 78.99,56.26 v1(78.99,55.93) ; v1(60.63,54.08) 60.13,54.58 J7.46
  BOTTOM w0.156: v1(60.63,54.08) 61.09,54.08 61.21,54.21 61.21,54.83 61.37,54.99 61.69,54.99 61.85,54.83 61.85,54.26 62.01,54.1 62.36,54.1 62.82,54.56 65.74,54.56 66.29,55.12 77.72,55.12 78.18,55.58 78.18,55.8 77.97,56.01 77.97,56.23 78.22,56.48 78.45,56.48 v1(78.99,55.93)
GMAC1_TXEN_M1: length 29.3
  TOP w0.156: U16.19 v1(81.03,55.93) ; v1(59.15,55.12) 59.13,55.13 J7.42
  BOTTOM w0.156: v1(81.03,55.93) 78.79,58.16 77.6,58.16 76.07,56.64 65.05,56.64 64.89,56.8 64.89,57.25 64.74,57.4 64.42,57.4 64.27,57.25 64.27,56.8 64.11,56.64 63.35,56.64 62.28,55.58 60.28,55.58 59.82,55.12 v1(59.15,55.12)
GPIO2_B7: length 114.2
  TOP w0.156: R48.2 124.84,19.56 124.46,19.94 120.27,19.94 119.63,19.3 119.63,16.89 118.62,15.87 114.17,15.87 113.16,16.89 113.16,23.24 v1(112.39,24) ; J7.47 v1(60.63,60.11)
  BOTTOM w0.156: v1(60.63,60.11) 61.11,59.63 61.11,58.89 60.39,58.16 57.02,58.16 55.63,56.77 55.63,48.89 60.71,43.81 63.12,43.81 76.33,30.61 94.54,30.61 95.94,32 112.27,32 113.41,30.86 113.41,27.81 112.39,26.8 v1(112.39,24)
GPIO2_C0: length 111.5
  TOP w0.156: R49.2 120.64,19.04 120.27,18.67 120.27,16.64 118.87,15.24 113.92,15.24 112.52,16.64 112.52,22.86 v1(111.38,24) ; J7.49 61.13,59.59 v1(60.63,59.09)
  BOTTOM w0.156: v1(111.38,24) 111.38,26.54 112.9,28.07 112.9,30.35 111.89,31.37 96.19,31.37 94.92,30.1 76.12,30.1 62.91,43.31 60.58,43.31 54.65,49.24 54.65,56.55 56.64,58.55 60.08,58.55 v1(60.63,59.09)
HDMI_5V: length 34.1
  TOP w0.381: v1(59.44,68.96) 60.07,68.32 v1(64.64,68.32) 68.77,68.32 v1(71.18,65.91)
  BOTTOM w0.254: R159.1 71.9,64.41 Q10.1 v1(71.18,65.91) ; Q9.1 56.58,65.34 57.14,65.9 R157.1 57.78,67.31 v1(59.44,68.96)
  BOTTOM w0.508: U25.18 61.84,68.34 63.88,66.29 D37.2 C129.1 ; C129.1 65.35,65.9 D32.1 ; C129.1 64.9,68.07 v1(64.64,68.32)
HDMI_TX0N_PORT: length 46.4
  TOP w0.124: J5.48 35.63,56.46 35.55,56.39 35.55,54.23 v1(35.69,54.1)
  BOTTOM w0.124: U25.9 60.42,77.25 59.8,77.25 56.42,73.86 55.82,73.86 55.73,73.78 U27.7 U27.4 53.98,73.78 53.9,73.86 53.63,73.86 51.44,71.67 51.44,69.47 50.98,69.01 48.58,69.01 arc(48.52,68.99) 48.49,68.92 arc(48.46,68.86) 48.4,68.83 48.09,68.83 arc(48.02,68.86) 48,68.92 arc(47.97,68.99) 47.9,69.01 45.77,69.01 arc(45.73,69.01) 45.7,68.98 45.09,68.37 45.09,67.97 arc(45.12,67.88) 45.21,67.84 arc(45.3,67.81) 45.34,67.72 45.34,67.47 arc(45.3,67.39) 45.21,67.35 arc(45.12,67.31) 45.09,67.22 45.09,66.98 arc(45.12,66.89) 45.21,66.85 arc(45.3,66.81) 45.34,66.73 45.34,66.48 arc(45.3,66.39) 45.21,66.36 arc(45.12,66.32) 45.09,66.23 45.09,65.99 arc(45.12,65.9) 45.21,65.86 arc(45.3,65.82) 45.34,65.73 45.34,65.49 arc(45.3,65.4) 45.21,65.36 arc(45.12,65.33) 45.09,65.24 45.09,65 arc(45.12,64.91) 45.21,64.87 arc(45.3,64.83) 45.34,64.74 45.34,64.5 arc(45.3,64.41) 45.21,64.37 arc(45.12,64.34) 45.09,64.25 45.09,63.8 42.3,61.01 41.69,61.01 39.66,58.98 37.73,58.98 37.34,58.6 arc(37.3,58.49) 37.34,58.38 arc(37.39,58.28) 37.34,58.17 37.21,58.03 arc(37.1,57.99) 36.99,58.03 arc(36.89,58.08) 36.78,58.03 36.64,57.9 arc(36.6,57.79) 36.64,57.68 arc(36.69,57.58) 36.64,57.47 36.51,57.33 arc(36.4,57.29) 36.29,57.33 arc(36.19,57.38) 36.08,57.33 35.54,56.8 35.54,54.24 v1(35.69,54.1)
HDMI_TX0P_PORT: length 44.9
  TOP w0.124: v1(35.03,54.1) 35.23,54.3 35.23,56.33 35.13,56.43 J5.46
  BOTTOM w0.124: v1(35.03,54.1) 35.22,54.29 35.22,56.93 37.59,59.31 39.52,59.31 41.56,61.34 42.16,61.34 44.76,63.93 44.76,68.51 45.59,69.34 50.85,69.34 51.11,69.6 51.11,71.81 53.49,74.19 53.87,74.19 53.96,74.28 U27.5 U27.6 55.73,74.28 55.82,74.19 56.29,74.19 59.67,77.57 60.42,77.57 U25.7
HDMI_TX1N_PORT: length 45.3
  TOP w0.124: J5.44 34.63,56.15 v1(34.72,56.06)
  BOTTOM w0.124: U25.6 60.23,78.57 60.1,78.7 60.1,78.86 59.98,78.99 59.76,78.99 59.56,78.79 59.56,78.4 57.08,75.92 55.82,75.92 55.73,75.83 U26.10 U26.1 54.09,75.83 54.02,75.9 53.8,75.9 53.63,75.72 arc(53.59,75.63) 53.63,75.53 arc(53.66,75.44) 53.63,75.34 53.47,75.18 arc(53.37,75.14) 53.27,75.18 arc(53.18,75.22) 53.08,75.18 52.92,75.02 arc(52.88,74.93) 52.92,74.83 arc(52.96,74.74) 52.92,74.64 52.76,74.48 arc(52.67,74.44) 52.57,74.48 arc(52.48,74.52) 52.38,74.48 52.22,74.32 arc(52.18,74.22) 52.22,74.13 arc(52.26,74.03) 52.22,73.94 52.06,73.78 arc(51.97,73.74) 51.87,73.78 arc(51.78,73.82) 51.68,73.78 51.52,73.62 arc(51.48,73.52) 51.52,73.43 arc(51.56,73.33) 51.52,73.24 51.36,73.08 arc(51.27,73.04) 51.17,73.08 arc(51.08,73.12) 50.98,73.08 50.82,72.92 arc(50.78,72.82) 50.82,72.73 arc(50.86,72.63) 50.82,72.54 50.66,72.38 arc(50.57,72.34) 50.47,72.38 50.45,72.39 arc(50.37,72.43) 50.3,72.39 50.22,72.32 49.67,72.32 arc(49.6,72.29) 49.58,72.23 arc(49.55,72.16) 49.49,72.13 49.17,72.13 arc(49.11,72.16) 49.08,72.23 arc(49.06,72.29) 48.99,72.32 48.68,72.32 arc(48.61,72.29) 48.59,72.23 arc(48.56,72.16) 48.5,72.13 48.18,72.13 arc(48.12,72.16) 48.09,72.23 arc(48.06,72.29) 48,72.32 47.51,72.32 44.14,68.95 44.14,64.21 41.96,62.03 39.12,62.03 35.31,58.22 34.49,58.22 34.24,57.97 34.24,57.15 34.49,56.89 34.49,56.29 v1(34.72,56.06)
HDMI_TX1P_PORT: length 43.8
  TOP w0.124: J5.42 34.13,56.12 v1(34.06,56.06)
  BOTTOM w0.124: v1(34.06,56.06) 34.16,56.16 34.16,56.76 33.91,57.01 33.91,58.1 34.35,58.55 35.18,58.55 38.99,62.36 41.83,62.36 43.81,64.34 43.81,69.09 47.37,72.64 50.08,72.64 53.67,76.23 54,76.23 54.11,76.33 U26.2 U26.9 55.73,76.33 55.82,76.25 56.94,76.25 59.24,78.54 59.24,78.92 59.62,79.31 59.98,79.31 60.1,79.44 60.1,79.6 60.23,79.73 U25.4
HDMI_TX2N_PORT: length 44.3
  TOP w0.124: J5.40 33.63,58.9 v1(33.78,59.05)
  BOTTOM w0.124: v1(33.78,59.05) 33.96,59.23 34.6,59.23 34.78,59.41 arc(34.87,59.45) 34.97,59.41 arc(35.06,59.37) 35.16,59.41 35.32,59.57 arc(35.36,59.67) 35.32,59.76 arc(35.28,59.86) 35.32,59.95 35.48,60.11 arc(35.57,60.15) 35.67,60.11 arc(35.76,60.07) 35.86,60.11 36.02,60.27 arc(36.06,60.37) 36.02,60.46 arc(35.98,60.56) 36.02,60.65 36.18,60.81 arc(36.27,60.85) 36.37,60.81 arc(36.46,60.78) 36.56,60.81 36.72,60.97 arc(36.76,61.07) 36.72,61.17 arc(36.68,61.26) 36.72,61.36 36.88,61.52 arc(36.97,61.56) 37.07,61.52 arc(37.16,61.48) 37.26,61.52 37.42,61.68 arc(37.46,61.77) 37.42,61.87 arc(37.38,61.96) 37.42,62.06 38.41,63.04 40.14,63.04 40.77,63.67 40.77,64.05 42.36,65.65 42.36,68.4 47.17,73.2 49.41,73.2 50.89,74.69 arc(51,74.73) 51.1,74.69 arc(51.21,74.64) 51.32,74.69 51.46,74.82 arc(51.5,74.93) 51.46,75.04 arc(51.41,75.15) 51.46,75.25 51.63,75.43 arc(51.74,75.48) 51.85,75.43 arc(51.96,75.39) 52.06,75.43 52.2,75.57 arc(52.24,75.67) 52.2,75.78 arc(52.15,75.89) 52.2,76 52.33,76.13 arc(52.44,76.18) 52.55,76.13 arc(52.66,76.09) 52.77,76.13 52.9,76.27 arc(52.94,76.38) 52.9,76.48 arc(52.86,76.59) 52.9,76.7 53.62,77.41 53.79,77.41 53.87,77.33 U26.4 U26.7 55.73,77.33 55.82,77.42 56.09,77.42 56.46,77.8 56.46,80.64 57.41,81.59 59.05,81.59 59.81,80.82 60.31,80.82 U25.3
HDMI_TX2P_PORT: length 42.8
  TOP w0.124: J5.38 33.13,58.94 v1(33.02,59.05)
  BOTTOM w0.124: v1(33.02,59.05) 33.53,59.56 34.46,59.56 38.27,63.37 40.01,63.37 40.44,63.81 40.44,64.19 42.04,65.78 42.04,68.53 47.04,73.53 49.27,73.53 50.66,74.92 arc(50.66,74.92) 50.66,74.92 53.48,77.74 53.78,77.74 53.87,77.83 U26.5 U26.6 55.73,77.83 55.82,77.75 55.95,77.75 56.13,77.93 56.13,80.77 57.28,81.91 59.18,81.91 59.94,81.15 60.54,81.15 U25.1
HDMI_TX_CEC_PORT: length 14.2
  BOTTOM w0.156: U25.13 59.41,74.52 55.63,70.74 54.36,70.74 53.85,70.23 D36.2 53.33,68.95 52.83,68.45 52.83,67.51 51.77,66.45 Q8.3
HDMI_TX_HPD_PORT: length 7.2
  BOTTOM w0.156: R153.2 R154.1 D33.2 60.83,71.05 U25.19
HDMI_TX_HPDIN: length 44.4
  TOP w0.156: J5.34 32.13,54.6 v1(31.63,54.1)
  BOTTOM w0.156: R153.1 62.87,63.63 62.23,62.99 48.51,62.99 46.12,60.6 46.12,56.24 44.11,54.23 41.91,54.23 39.75,52.07 33.66,52.07 v1(31.63,54.1)
HDMI_TXCLKN_PORT: length 46
  TOP w0.124: J5.50 36.13,56.68 36.2,56.61 36.2,56.27 v1(36.05,56.12)
  BOTTOM w0.124: U25.12 60.23,75.1 60.1,75.23 60.1,75.39 59.98,75.52 59.47,75.52 56.32,72.36 55.82,72.36 55.73,72.28 U27.10 U27.1 53.98,72.28 53.9,72.36 53.7,72.36 52.32,70.99 52.32,68.88 50.94,67.49 47.13,67.49 46.56,66.92 46.56,63.87 43.81,61.13 43.81,59.94 44.14,59.62 44.14,57.39 43.57,56.82 42.35,56.82 42.04,57.14 42.04,57.84 41.91,57.96 41.66,57.96 41.54,57.84 41.54,57.14 41.22,56.82 40.7,56.82 40.39,57.14 40.39,57.84 40.27,57.96 39.63,57.96 37.97,56.31 37.97,55.75 37.26,55.04 36.69,55.04 36.16,55.58 36.16,56.01 v1(36.05,56.12)
HDMI_TXCLKP_PORT: length 47
  TOP w0.124: J5.52 36.63,56.69 36.53,56.6 36.53,56.3 v1(36.71,56.12)
  BOTTOM w0.124: U25.10 60.23,76.26 60.1,76.14 60.1,75.97 59.98,75.85 59.34,75.85 56.18,72.69 55.82,72.69 55.73,72.78 U27.9 U27.2 53.96,72.78 53.87,72.69 53.56,72.69 52,71.13 52,69.01 50.8,67.82 49.57,67.82 arc(49.48,67.85) 49.45,67.94 arc(49.41,68.03) 49.32,68.07 49.08,68.07 arc(48.99,68.03) 48.95,67.94 arc(48.91,67.85) 48.82,67.82 48.58,67.82 arc(48.49,67.85) 48.45,67.94 arc(48.42,68.03) 48.33,68.07 48.08,68.07 arc(48,68.03) 47.96,67.94 arc(47.92,67.85) 47.83,67.82 46.86,67.82 46.23,67.18 46.23,64.01 43.49,61.27 43.49,59.81 43.81,59.48 43.81,57.53 43.43,57.15 42.49,57.15 42.36,57.27 42.36,57.98 42.05,58.29 41.53,58.29 41.21,57.98 41.21,57.27 41.09,57.15 40.84,57.15 40.72,57.27 40.72,57.98 40.4,58.29 39.5,58.29 39.24,58.03 arc(39.11,57.98) 38.98,58.03 arc(38.85,58.08) 38.73,58.03 38.63,57.93 arc(38.58,57.81) 38.63,57.68 arc(38.68,57.55) 38.63,57.43 38.53,57.33 arc(38.41,57.28) 38.28,57.33 arc(38.15,57.38) 38.03,57.33 37.93,57.23 arc(37.88,57.11) 37.93,56.98 arc(37.98,56.85) 37.93,56.72 37.65,56.44 37.65,55.89 37.13,55.37 36.83,55.37 36.48,55.72 36.48,55.89 v1(36.71,56.12)
HDMI_TXDDC_SCL_PORT: length 17.3
  BOTTOM w0.156: U25.15 58.89,73.37 55.5,69.98 55.12,69.98 54.86,69.72 D35.2 55.38,68.95 55.63,68.71 Q9.3 55.63,63.88 55.88,63.63 57.53,63.63 57.78,63.88 R157.2
HDMI_TXDDC_SDA_PORT: length 13.8
  BOTTOM w0.156: U25.16 62.59,72.79 66.43,68.95 D34.2 68.71,68.32 68.71,67.56 69.82,66.45 Q10.3 71.85,66.45 R159.2
HDMITX_CEC_M0: length 29
  TOP w0.156: v1(31.63,56.13) J5.32
  BOTTOM w0.156: v1(31.63,56.13) 34.68,53.08 39.24,53.08 41.53,55.37 43.69,55.37 45.16,56.84 45.16,60.92 R155.2 49.86,64.9 Q8.2
HDMITX_SCL: length 35.1
  TOP w0.156: J5.30 31.13,55.62 v1(31.63,55.12)
  BOTTOM w0.156: Q9.2 54.18,64.9 R156.2 53.47,64.01 52.96,63.5 48.39,63.5 45.59,60.71 45.59,56.51 43.94,54.86 41.78,54.86 39.5,52.58 34.17,52.58 v1(31.63,55.12)
HDMITX_SDA: length 52.4
  TOP w0.156: v1(31.63,53.08) 30.63,54.08 J5.28
  BOTTOM w0.156: Q10.2 68.79,64.9 R158.2 67.56,64.4 67.56,62.99 67.06,62.48 48.64,62.48 46.76,60.6 46.76,56.11 44.37,53.72 42.16,53.72 40.01,51.56 33.15,51.56 v1(31.63,53.08)
HOST1_DM: length 13.9
  BOTTOM w0.158: J18.2 93.97,80.37 93.81,80.21 93.81,79.79 94.41,79.19 94.41,78.67 95.41,77.67 95.41,76.56 94.85,75.99 94.85,73.97 95.19,73.63 95.19,71.46 U19.7 U19.4 95.26,70.07 95.19,70 95.19,69.48 94.92,69.21 94.92,68.9 R136.1
HOST1_DP: length 13.9
  BOTTOM w0.158: R137.1 94.56,68.9 94.56,69.36 94.83,69.63 94.83,70 94.76,70.07 U19.5 U19.6 94.83,71.46 94.83,73.48 94.49,73.82 94.49,76.21 93.73,76.97 93.73,77.67 92.85,78.55 92.85,79.19 93.45,79.79 93.45,80.16 93.24,80.37 J18.3
HP_DET: length 93.7
  TOP w0.203: J6.80 68.63,26.08 v1(70.71,28.17)
  ART03 w0.203: v1(34.04,68.28) 25.74,68.28 22.48,65.02 22.48,46.86 26.42,42.92 49.53,42.92 v1(56.52,35.94)
  BOTTOM w0.203: v1(34.04,68.28) C173.1 34.04,68.97 R215.1 ; v1(56.52,35.94) 62.94,35.94 v1(70.71,28.17)
HP_SNS: length 85
  TOP w0.203: v1(35.69,80.64) 35.69,84.33 J28.1 ; J4.36 32.63,47.49 v1(32.64,47.5)
  BOTTOM w0.203: v1(35.69,80.64) 35.46,80.42 35.46,72.48 R216.1 35.81,70.86 35.81,68.58 33.76,66.52 33.76,63.11 30.78,60.14 30.78,57.5 30.36,57.07 30.36,51.94 33.15,49.15 33.15,48.01 32.64,47.5 v1(32.64,47.5)
  BOTTOM w0.381: R218.1 53.17,86.78 J29.1 J28.1
HPL_OUT: length 45
  TOP w0.203: C175.1 33.14,65.78 v1(33.15,65.78) ; J4.34 32.13,25.91 32.26,26.03 32.26,47.16 32.13,47.29 32.13,48 v1(32.64,48.51)
  BOTTOM w0.203: v1(32.64,48.51) 32.64,49.02 30,51.66 30,57.22 30.43,57.64 30.43,60.28 33.4,63.26 33.4,65.53 v1(33.15,65.78)
HPR_OUT: length 49.1
  TOP w0.203: v1(38.23,65.78) C176.1 ; J4.38 33.13,25.92 32.99,26.07 32.99,46.83 v1(33.66,47.5)
  BOTTOM w0.203: v1(38.23,65.78) 34.54,65.78 34.11,65.35 34.11,62.96 31.14,59.99 31.14,57.35 30.72,56.93 30.72,52.21 33.66,49.27 v1(33.66,47.5)
HUB_3V3: length 5.5
  TOP w0.254: v1(106.74,51.32) U22.20 ; U22.1 106.23,54.17 v1(106.43,53.97)
  BOTTOM w0.254: v1(106.74,51.32) 106.31,51.32 105.4,50.41 R145.1 R144.1
HUB_DM1: length 26.1
  TOP w0.158: v1(95.02,61.42) 94.87,61.28 94.87,60.7 96.14,59.43 96.14,57.28 97.28,56.13 97.28,54.74 98.04,53.97 98.04,52.96 99.75,51.25 100.78,51.25 100.85,51.32 U22.11
  BOTTOM w0.158: R129.2 89.17,67.17 89.17,63.73 92.43,60.47 94.56,60.47 94.93,60.84 94.93,61.33 v1(95.02,61.42)
HUB_DM2: length 23.5
  TOP w0.158: U22.9 101.09,52.32 101.01,52.24 100.66,52.24 v1(100.2,52.7)
  BOTTOM w0.158: R138.2 106.79,67.17 106.79,66.94 106.42,66.57 102.26,66.57 100.31,64.62 100.31,59.84 101.1,59.04 101.1,58.65 arc(101.16,58.52) 101.29,58.47 arc(101.42,58.41) 101.47,58.28 101.47,58.02 arc(101.42,57.89) 101.29,57.84 arc(101.16,57.78) 101.1,57.65 101.1,57.29 99.98,56.16 99.98,55.88 arc(100.03,55.76) 100.16,55.7 arc(100.27,55.66) 100.31,55.55 100.31,55.23 arc(100.27,55.12) 100.16,55.07 arc(100.03,55.02) 99.98,54.9 99.98,52.93 v1(100.2,52.7)
HUB_DM3: length 23.1
  TOP w0.158: v1(101.42,54.35) 100.8,53.74 100.8,53.48 100.96,53.32 U22.7
  BOTTOM w0.158: R131.2 108.95,67.3 108.95,66.02 108.35,65.42 102.64,65.42 101.6,64.38 101.6,60.2 102.47,59.33 102.47,55.61 101.85,54.99 101.35,54.99 101.18,54.82 101.18,54.6 v1(101.42,54.35)
HUB_DM4: length 4.4
  TOP w0.158: U22.5 103.01,54.98 102.62,55.37 100.32,55.37 R210.2
HUB_DP1: length 26.1
  TOP w0.158: v1(94.36,61.42) 94.51,61.27 94.51,60.55 95.78,59.29 95.78,57.13 96.92,55.98 96.92,54.59 97.68,53.82 97.68,52.81 99.6,50.89 100.75,50.89 100.82,50.82 U22.12
  BOTTOM w0.158: v1(94.36,61.42) 94.57,61.21 94.57,60.99 94.41,60.83 92.58,60.83 89.53,63.88 89.53,64.54 arc(89.57,64.63) 89.66,64.67 arc(89.75,64.71) 89.79,64.8 89.79,65.18 arc(89.75,65.27) 89.66,65.3 arc(89.57,65.34) 89.53,65.43 89.53,65.81 arc(89.57,65.9) 89.66,65.94 arc(89.75,65.98) 89.79,66.06 89.79,66.44 arc(89.75,66.53) 89.66,66.57 arc(89.57,66.61) 89.53,66.7 89.53,67.32 R130.2
HUB_DP2: length 23.6
  TOP w0.158: v1(99.44,52.7) 100.33,51.82 U22.10
  BOTTOM w0.158: v1(99.44,52.7) 99.62,52.88 99.62,56.31 100.74,57.44 100.74,58.89 99.95,59.69 99.95,64.77 102.11,66.93 106.27,66.93 106.43,67.09 106.43,67.41 106.27,67.57 R139.2
HUB_DP3: length 23.6
  TOP w0.158: v1(100.66,54.35) 100.44,54.14 100.44,53.33 100.94,52.82 U22.8
  BOTTOM w0.158: R132.2 108.58,67.19 108.58,66.17 108.2,65.78 102.49,65.78 101.24,64.53 101.24,60.05 102.11,59.18 102.11,55.76 101.7,55.35 101.2,55.35 100.81,54.97 100.81,54.51 v1(100.66,54.35)
HUB_DP4: length 3.5
  TOP w0.158: U22.6 102.51,54.83 102.35,54.99 99.94,54.99 R211.2
I2C0_SCL_PMIC: length 84.5
  TOP w0.156: J6.3 49.63,21.74 49.28,22.1 48.77,22.1 v1(48.13,22.73)
  ART03 w0.142: v1(48.13,22.73) 48.01,22.73 45.21,25.53 39.75,25.53 38.35,26.92 38.35,32.64 36.96,34.03 21.21,34.03 19.99,35.25 19.99,43.76 18.8,44.96 18.8,49.27 15.11,52.96 v1(15.11,72.01)
  BOTTOM w0.156: v1(15.11,72.01) 13.97,72.01 13.72,71.75 13.72,68.48 13.87,68.32 U12.6
I2C0_SDA_PMIC: length 91
  TOP w0.156: v1(49.15,22.73) 50.13,21.75 J6.5
  ART03 w0.142: v1(15.11,73.02) 14.1,72.01 14.1,53.21 18.29,49.02 18.29,44.58 19.14,43.72 19.14,35.47 21.08,33.53 36.83,33.53 37.78,32.57 37.78,26.73 39.5,25.02 45.08,25.02 47.88,22.22 48.64,22.22 v1(49.15,22.73)
  BOTTOM w0.156: U12.5 13.46,67.05 13.08,67.44 13.08,72.52 13.59,73.02 v1(15.11,73.02)
I2C1_SCL: length 161.8
  TOP w0.156: v1(51.13,18.16) 50.63,18.66 J6.7 ; v1(133.6,69.16) 132.57,68.12 J21.9 129.21,68.12 128.4,67.31 122.68,67.31 119.76,64.39 119.76,53.08 120.27,52.58 120.27,48.51 119.76,48 119.76,45.34 v1(120.27,44.83)
  ART03 w0.142: v1(120.27,44.83) 120.27,43.81 123.96,40.13 127.58,40.13 130.56,37.15 130.56,19.43 126.75,15.62 122.05,15.62 120.27,13.84 74.17,13.84 70.36,17.65 51.64,17.65 v1(51.13,18.16)
  BOTTOM w0.156: R163.2 128.14,71.37 129.36,70.16 J23.6 132.6,70.16 v1(133.6,69.16)
I2C1_SDA: length 157.7
  TOP w0.156: v1(132.59,69.16) 132.06,68.62 J21.10 129.08,68.62 128.27,67.82 122.55,67.82 119.25,64.52 119.25,52.58 119.76,52.07 119.76,49.15 119.25,48.64 v1(119.25,44.83) ; v1(51.13,19.18) J6.9
  ART03 w0.142: v1(119.25,44.83) 119.25,43.94 123.57,39.62 126.62,39.62 130.05,36.19 130.05,19.68 126.49,16.13 121.92,16.13 120.14,14.35 74.3,14.35 70.48,18.16 52.15,18.16 v1(51.13,19.18)
  BOTTOM w0.156: R167.2 128.27,70.36 128.97,69.66 J23.5 132.09,69.66 v1(132.59,69.16)
I2C2_SCL_M1: length 17.1
  TOP w0.156: v1(75.56,17.4) 74.8,18.16 62.36,18.16 61.63,18.89 J6.51
  BOTTOM w0.156: R222.2 v1(75.56,17.4)
I2C2_SDA_M1: length 19.4
  TOP w0.156: v1(78.61,17.4) 77.34,18.67 62.74,18.67 62.13,19.28 J6.53
  BOTTOM w0.156: R221.2 v1(78.61,17.4)
I2C3_SCL_M0: length 36
  TOP w0.156: R219.2 v1(96.27,22.35) ; J6.72 66.63,23.54 67.06,23.11 v1(67.06,22.1)
  ART03 w0.142: v1(67.06,22.1) 67.06,20.95 67.63,20.38 71.69,20.38 72.77,19.3 80.26,19.3 83.31,22.35 v1(96.27,22.35)
I2C3_SDA_M0: length 39.1
  TOP w0.156: R220.2 v1(97.28,22.35) ; J6.70 66.13,23.2 v1(65.02,22.1)
  ART03 w0.142: v1(97.28,22.35) 96.77,21.84 83.82,21.84 80.77,18.79 72.39,18.79 71.31,19.87 67.25,19.87 v1(65.02,22.1)
I2C4_SCL_M0: length 75.8
  TOP w0.156: J7.29 56.13,59.59 v1(55.63,59.09) ; v1(80.64,21.59) 79.25,20.19 79.25,14.63 78.84,14.22 69.57,14.22 J26.4
  BOTTOM w0.156: v1(55.63,59.09) 53.59,57.06 53.59,48.89 60.2,42.29 62.1,42.29 80.64,23.75 v1(80.64,21.59)
I2C4_SDA_M0: length 75.4
  TOP w0.156: v1(80.64,20.57) 79.88,19.81 79.88,14.1 78.99,13.21 69.47,13.21 68,11.74 J26.5 ; J7.31 v1(56.63,60.11)
  BOTTOM w0.156: v1(56.63,60.11) 56.11,59.6 56.11,58.78 54.1,56.77 54.1,49.15 60.52,42.73 62.42,42.73 81.15,24 81.15,21.08 v1(80.64,20.57)
I2C5_SCL_M0: length 116.3
  TOP w0.156: J7.25 55.13,59.59 v1(54.63,59.09) ; R165.2 127.17,46.03 J22.9 130.88,46.03 v1(131.19,45.72)
  ART03 w0.142: v1(54.63,59.09) 57.08,56.64 60.71,56.64 62.74,54.61 63.88,54.61 65.53,52.96 85.22,52.96 85.68,53.42 90.89,53.42 91.82,54.35 96.65,54.35 97.16,54.86 103.63,54.86 106.05,57.28 117.86,57.28 118.86,58.28 133.62,58.28 134.62,57.28 134.62,50.8 130.71,46.89 130.71,46.2 v1(131.19,45.72)
  BOTTOM w0.156: J24.6 131.7,53.39 131.75,53.44 132.33,53.44 132.59,53.19 132.59,51.18 131.7,50.29 131.7,46.23 v1(131.19,45.72)
I2C5_SDA_M0: length 111.7
  TOP w0.156: J7.27 v1(55.63,60.11) ; v1(131.19,46.61) 131.11,46.53 J22.10 126.82,46.53 R169.2
  ART03 w0.142: v1(55.63,60.11) 56.06,59.68 56.06,58.88 57.91,57.02 62.1,57.02 63.44,55.68 64.96,55.68 67.23,53.42 84.96,53.42 85.9,54.35 90.93,54.35 91.87,55.29 103.3,55.29 105.79,57.78 117.73,57.78 118.83,58.88 134.16,58.88 135.22,57.82 135.22,50.64 v1(131.19,46.61)
  BOTTOM w0.156: J24.5 131.17,52.89 131.44,52.62 131.44,50.67 131.19,50.42 v1(131.19,46.61)
LCD0_BL_PWM: length 146.5
  TOP w0.156: J5.9 v1(26.13,63.24) ; v1(117.22,46.86) 117.22,48.89 117.68,49.35 117.68,57.43 117.12,57.99 117.12,60.22 117.73,60.83 117.73,64.9 122.17,69.34 127.11,69.34 127.89,70.12 J21.13
  ART03 w0.142: v1(117.22,46.86) 115.44,46.86 111.12,42.54 93.22,42.54 92.46,41.78 70.1,41.78 69.6,41.27 55.88,41.27 50.8,46.35 27.18,46.35 26.13,47.4 v1(26.13,63.24)
LCD1_BL_PWM: length 127.5
  TOP w0.156: v1(27.13,64.26) 26.63,63.76 J5.11 ; J22.13 v1(128.91,48.02)
  ART03 w0.142: v1(27.13,64.26) 26.61,63.74 26.61,47.94 27.69,46.86 51.05,46.86 55.63,42.29 92.33,42.29 93.22,43.18 111,43.18 115.32,47.5 128.38,47.5 v1(128.91,48.02)
MDIN0_PHY: length 12.8
  TOP w0.124: U16.2 81.79,62.94 81.79,64.01 80.14,65.66 80.14,72.97 80.01,73.09 79.84,73.09 J17.3
MDIN1_PHY: length 21.3
  TOP w0.124: J17.7 73.87,74.9 74.78,75.82 75.69,75.82 76.15,75.36 76.15,73.96 77.5,72.61 77.5,70.33 78.74,69.09 78.74,64.34 81.3,61.78 U16.5
MDIN2_PHY: length 16
  TOP w0.124: U16.7 80.74,61.21 77.6,64.35 77.6,68.58 74.98,71.2 74.98,73.2 75.14,73.36 J17.6
MDIN3_PHY: length 17.5
  TOP w0.124: U16.10 79.89,60.41 79.67,60.63 79.37,60.63 76.51,63.49 76.51,67.05 72.44,71.11 72.44,72.93 72.32,73.06 72.04,73.06 71.33,72.34 J17.9
MDIP0_PHY: length 12.8
  TOP w0.124: J17.2 80.22,73.35 80.46,73.1 80.46,65.79 82.12,64.14 82.12,63.18 U16.1
MDIP1_PHY: length 21.3
  TOP w0.124: J17.4 77.68,76.25 77.22,76.71 75.56,76.71 75.44,76.58 75.44,76.27 75.56,76.15 75.83,76.15 76.48,75.49 76.48,74.14 77.83,72.79 77.83,70.46 79.07,69.22 79.07,64.48 81.54,62.01 U16.4
MDIP2_PHY: length 16
  TOP w0.124: U16.6 80.97,61.44 77.92,64.49 77.92,68.72 75.31,71.33 75.31,73.07 75.52,73.28 75.95,73.28 76.41,72.82 J17.5
MDIP3_PHY: length 17.5
  TOP w0.124: U16.9 79.81,60.96 79.5,60.96 76.83,63.63 76.83,67.18 72.77,71.25 72.77,73.15 72.6,73.33 J17.8
MIC_INN: length 62.1
  TOP w0.124: J4.30 31.13,25.81 31.04,25.9 31.04,48.61 32.05,49.62 44.04,49.62 46.11,51.69 46.11,61.65 48.68,64.22 48.68,64.67 R217.1 49.03,65.41 49.31,65.7 C174.2 49.31,66.88 49.03,67.17 D44.2 48.68,68.04 48.68,70.52 48.9,70.74 J30.1
MIC_INP: length 78.6
  TOP w0.124: 47.37,70.74 48.18,70.74 48.35,70.57 48.35,68.04 D41.2 48,67.17 47.71,66.88 C174.1 47.71,65.7 48,65.41 R213.2 48.35,64.67 48.35,64.35 45.78,61.78 45.78,51.83 43.9,49.95 31.92,49.95 30.72,48.75 30.72,25.9 30.63,25.81 J4.28
  TOP w0.254: J29.2 48.55,82.38 J29.5 48.76,80.68 J29.3 48.55,76.88 J29.4 48.55,73.45 47.37,72.26 47.37,70.74
MINIPCIE_3V3: length 29.1
  TOP w0.381: J27.2 115.6,64.1 v1(115.19,64.51) ; J27.24 v1(103.6,61.59) ; J27.52 v1(92.4,64.51)
  BOTTOM w0.254: 111.63,64.26 111.51,64.39 R205.1 ; 109.17,63.12 109.17,53.79 R201.1 C155.1
  BOTTOM w0.381: v1(97.66,69.85) 98.3,69.21 C167.1 ; v1(115.19,64.51) C170.1 114.55,64.26 111.63,64.26 111.13,63.76 C161.1 ; v1(103.6,61.59) 103.63,61.62 C169.1 ; C168.1 92.46,64.46 v1(92.4,64.51)
  vias: v1(102.59,61.59)
MINIPCIE_NWDISABLE: length 50.2
  TOP w0.156: v1(63.63,59.09) 64.13,59.59 J7.61
  ART03 w0.142: v1(105.66,61.59) 105.66,61.09 102.87,58.29 96.14,58.29 95.5,57.66 90.55,57.66 90.12,57.23 85.6,57.23 84.25,55.88 82.3,55.88 81.79,56.39 78.23,56.39 77.7,55.86 68.22,55.86 65.91,58.16 64.56,58.16 v1(63.63,59.09)
  BOTTOM w0.156: R208.2 v1(105.66,61.59)
MIPI0_PWR_EN: length 74.2
  TOP w0.156: R171.1 120.8,56.55 120.8,47.39 v1(120.27,46.86) ; J6.74 67.13,27.63 79.38,39.88 v1(80.64,39.88)
  ART03 w0.142: v1(80.64,39.88) 81.53,40.77 110.23,40.77 115.82,46.35 117.6,46.35 118.11,46.86 v1(120.27,46.86)
MIPI1_PWR_EN: length 115
  TOP w0.156: J5.16 27.63,55.44 25.27,53.08 v1(24.11,53.08) ; v1(113.03,37.72) 118.03,37.72 119.8,35.95 R170.1
  ART03 w0.142: v1(113.03,37.72) 113.03,38.48 112.27,39.24 111.51,39.24 111,38.73 56.26,38.73 50.93,44.07 27.05,44.07 24.11,47.01 v1(24.11,53.08)
